(* Logix 5000 project; controller Test vendor 1 type 14 code 92 rev 33.11; software revision 33.03; part 2 of 2 *)
(* tags used below, declared in another part *)
   B25 : Banner_B25_v4;
   Port_Data : Banner_IOL_Port_v4;
   Port : DINT;
   Local_Control : DINT;
   Command_Being_Processed : BOOL;
   Index_Write_Inprocess : INT;
   Inprocess_Index : DINT;
(* Banner_B25_Param_v4, continued *)

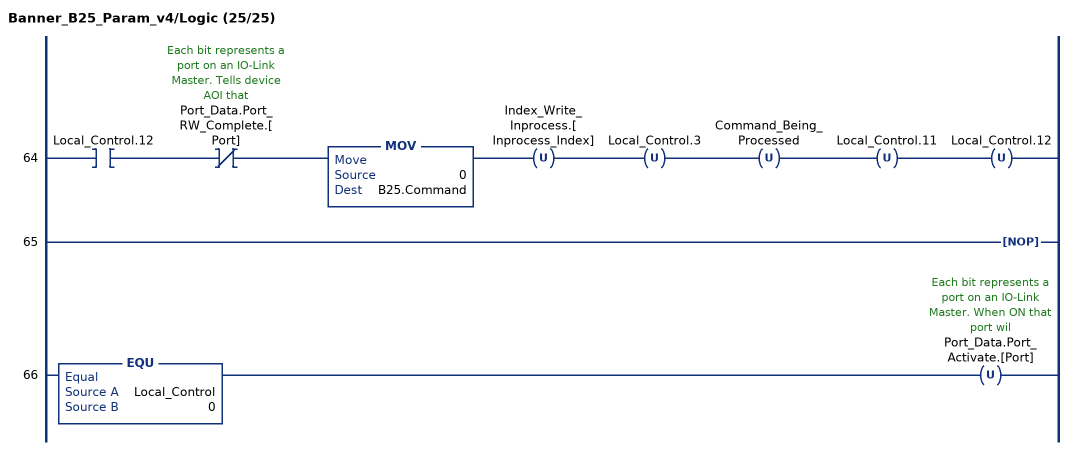
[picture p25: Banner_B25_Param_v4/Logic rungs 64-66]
   64: XIC(Local_Control.12)XIO(Port_Data.Port_RW_Complete.[Port])MOV(0,B25.Command)OTU(Index_Write_Inprocess.[Inprocess_Index])OTU(Local_Control.3)OTU(Command_Being_Processed)OTU(Local_Control.11)OTU(Local_Control.12);
   65: NOP();
   66: EQU(Local_Control,0)OTU(Port_Data.Port_Activate.[Port]);
END_ROUTINE
END_ADD_ON_INSTRUCTION

ADD_ON_INSTRUCTION Banner_B25_PD_v4   (* revision 4.0, vendor Banner Engineering *)
// Take raw process data and convert it to usable values.
VAR_INPUT
   SINT0 : SINT; {required}
END_VAR
VAR_IN_OUT
   PD : Banner_B25_PDI_v4; {required}
END_VAR

ROUTINE Logic   (* ladder *)
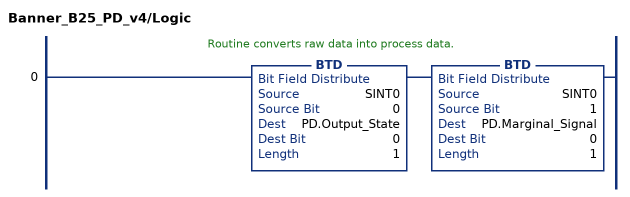
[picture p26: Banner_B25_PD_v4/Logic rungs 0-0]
   // Routine converts raw data into process data.
   0: BTD(SINT0,0,PD.Output_State,0,1)BTD(SINT0,1,PD.Marginal_Signal,0,1);
END_ROUTINE
END_ADD_ON_INSTRUCTION

ADD_ON_INSTRUCTION Banner_DXMR_IOLM_Param_v4   (* revision 4.3, vendor Banner Engineering *)
// AOI that controls a Banner IO-Link Master with Banner devices for parameter data operations.
// Revision note:
// Updated name of AOI.
VAR_IN_OUT
   IOLM : Banner_IOLM_v4; {required}
END_VAR
VAR
   Lock : DINT; {access None}
   Byte_Length : SINT; {access None}
   Current_Port : INT; {access None}   // Current port to communicate with via the IO-Link Master.
   Timer1 : TIMER := (PRE := 500); {access None}
   Error_Index : DINT; {access None}
   Timer2 : TIMER := (PRE := 5000); {access None}
   Temp_Index : INT; {access None}
   ErrCount : DINT; {access None}
   Timer4 : TIMER := (PRE := 2000); {access None}
   Timer5 : TIMER := (PRE := 2000); {access None}
   Timer3 : TIMER := (PRE := 2000); {access None}
   Timer6 : TIMER := (PRE := 3000); {access None}
   Timer7 : TIMER := (PRE := 3000); {access None}
   Timer8 : TIMER := (PRE := 3000); {access None}
END_VAR

ROUTINE Logic   (* ladder *)
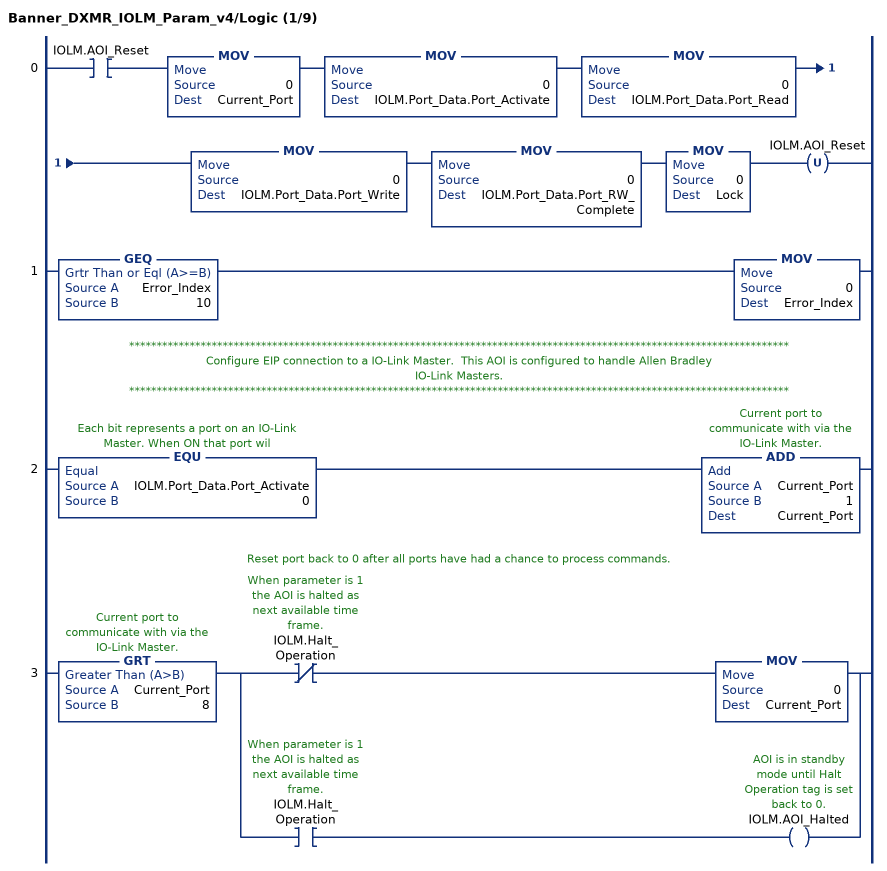
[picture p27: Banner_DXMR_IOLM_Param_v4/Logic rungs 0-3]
   0: XIC(IOLM.AOI_Reset)MOV(0,Current_Port)MOV(0,IOLM.Port_Data.Port_Activate)MOV(0,IOLM.Port_Data.Port_Read)MOV(0,IOLM.Port_Data.Port_Write)MOV(0,IOLM.Port_Data.Port_RW_Complete)MOV(0,Lock)OTU(IOLM.AOI_Reset);
   1: GEQ(Error_Index,10)MOV(0,Error_Index);
   // ************************************************************************************************************************
   // Configure EIP connection to a IO-Link Master.  This AOI is configured to handle Allen Bradley
   // IO-Link Masters.
   // ************************************************************************************************************************
   2: EQU(IOLM.Port_Data.Port_Activate,0)ADD(Current_Port,1,Current_Port);
   // Reset port back to 0 after all ports have had a chance to process commands.
   3: GRT(Current_Port,8)[XIO(IOLM.Halt_Operation) MOV(0,Current_Port) ,XIC(IOLM.Halt_Operation) OTE(IOLM.AOI_Halted) ];
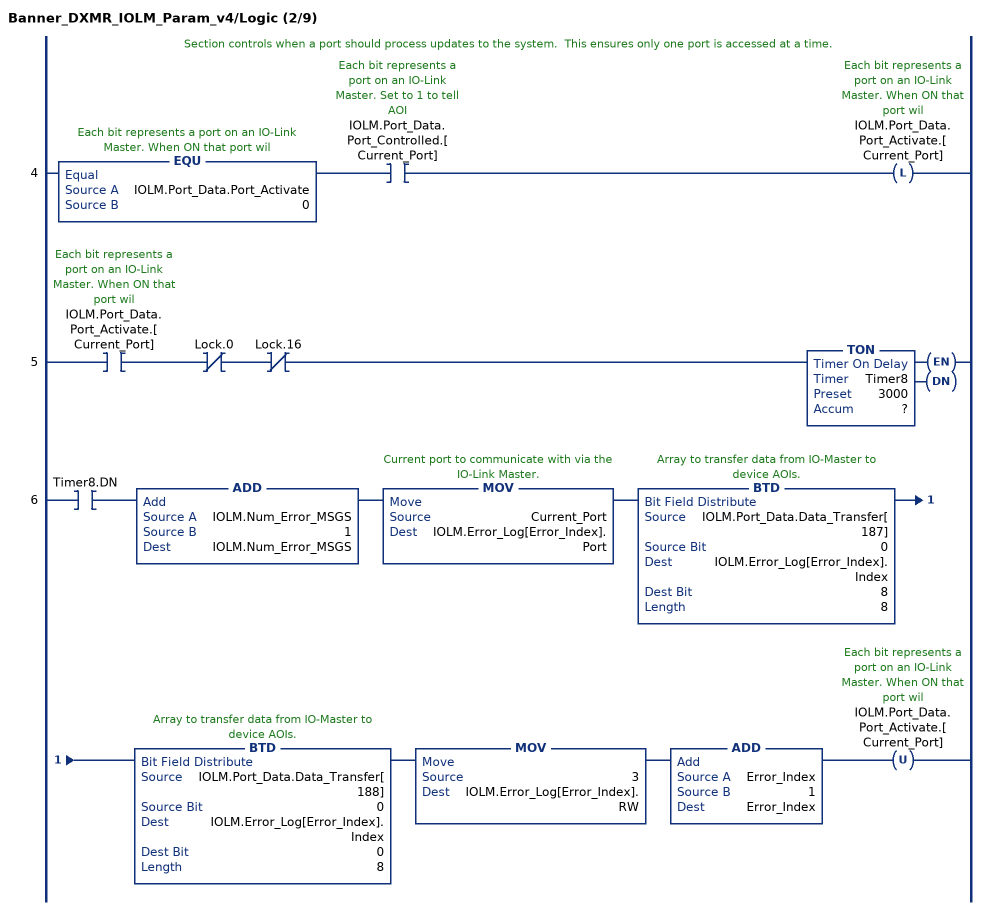
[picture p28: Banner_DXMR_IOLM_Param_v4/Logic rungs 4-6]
   // Section controls when a port should process updates to the system.  This ensures only one port is accessed at a time.
   4: EQU(IOLM.Port_Data.Port_Activate,0)XIC(IOLM.Port_Data.Port_Controlled.[Current_Port])OTL(IOLM.Port_Data.Port_Activate.[Current_Port]);
   5: XIC(IOLM.Port_Data.Port_Activate.[Current_Port])XIO(Lock.0)XIO(Lock.16)TON(Timer8,?,?);
   6: XIC(Timer8.DN)ADD(IOLM.Num_Error_MSGS,1,IOLM.Num_Error_MSGS)MOV(Current_Port,IOLM.Error_Log[Error_Index].Port)BTD(IOLM.Port_Data.Data_Transfer[187],0,IOLM.Error_Log[Error_Index].Index,8,8)BTD(IOLM.Port_Data.Data_Transfer[188],0,IOLM.Error_Log[Error_Index].Index,0,8)MOV(3,IOLM.Error_Log[Error_Index].RW)ADD(Error_Index,1,Error_Index)OTU(IOLM.Port_Data.Port_Activate.[Current_Port]);
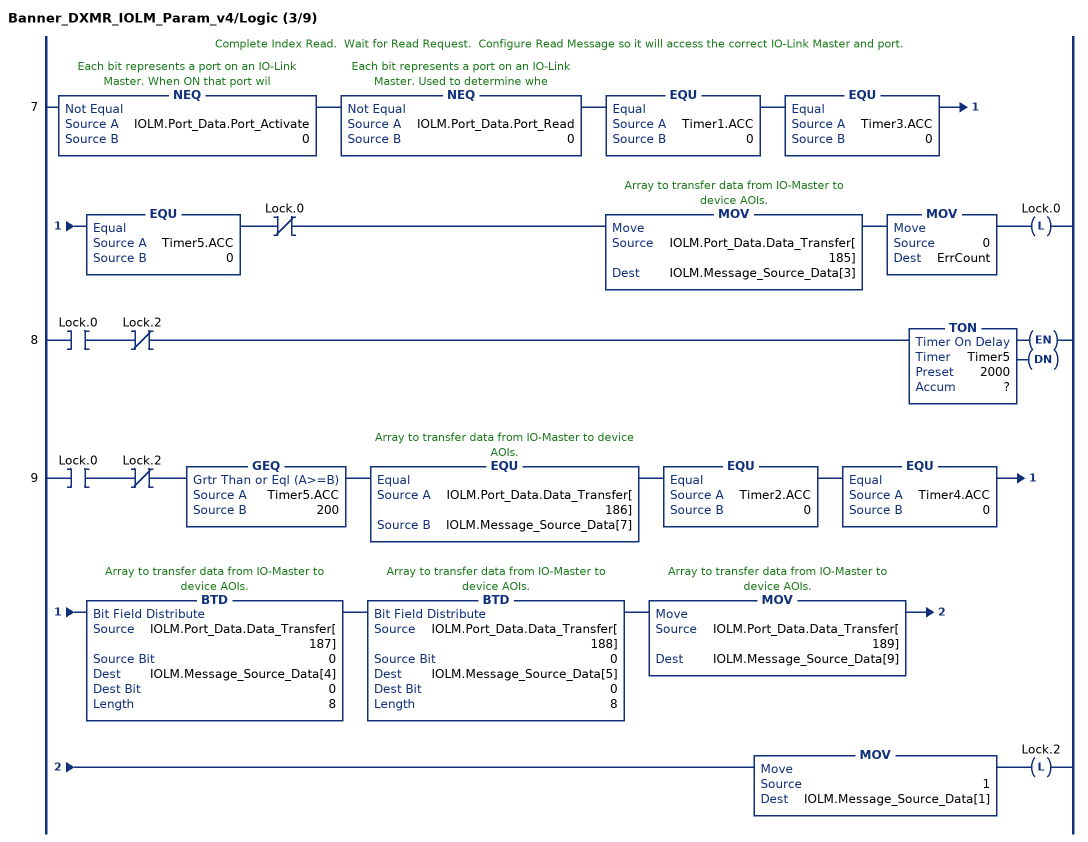
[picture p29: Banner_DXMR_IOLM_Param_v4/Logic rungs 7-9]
   // Complete Index Read.  Wait for Read Request.  Configure Read Message so it will access the correct IO-Link Master and port.
   7: NEQ(IOLM.Port_Data.Port_Activate,0)NEQ(IOLM.Port_Data.Port_Read,0)EQU(Timer1.ACC,0)EQU(Timer3.ACC,0)EQU(Timer5.ACC,0)XIO(Lock.0)MOV(IOLM.Port_Data.Data_Transfer[185],IOLM.Message_Source_Data[3])MOV(0,ErrCount)OTL(Lock.0);
   8: XIC(Lock.0)XIO(Lock.2)TON(Timer5,?,?);
   9: XIC(Lock.0)XIO(Lock.2)GEQ(Timer5.ACC,200)EQU(IOLM.Port_Data.Data_Transfer[186],IOLM.Message_Source_Data[7])EQU(Timer2.ACC,0)EQU(Timer4.ACC,0)BTD(IOLM.Port_Data.Data_Transfer[187],0,IOLM.Message_Source_Data[4],0,8)BTD(IOLM.Port_Data.Data_Transfer[188],0,IOLM.Message_Source_Data[5],0,8)MOV(IOLM.Port_Data.Data_Transfer[189],IOLM.Message_Source_Data[9])MOV(1,IOLM.Message_Source_Data[1])OTL(Lock.2);
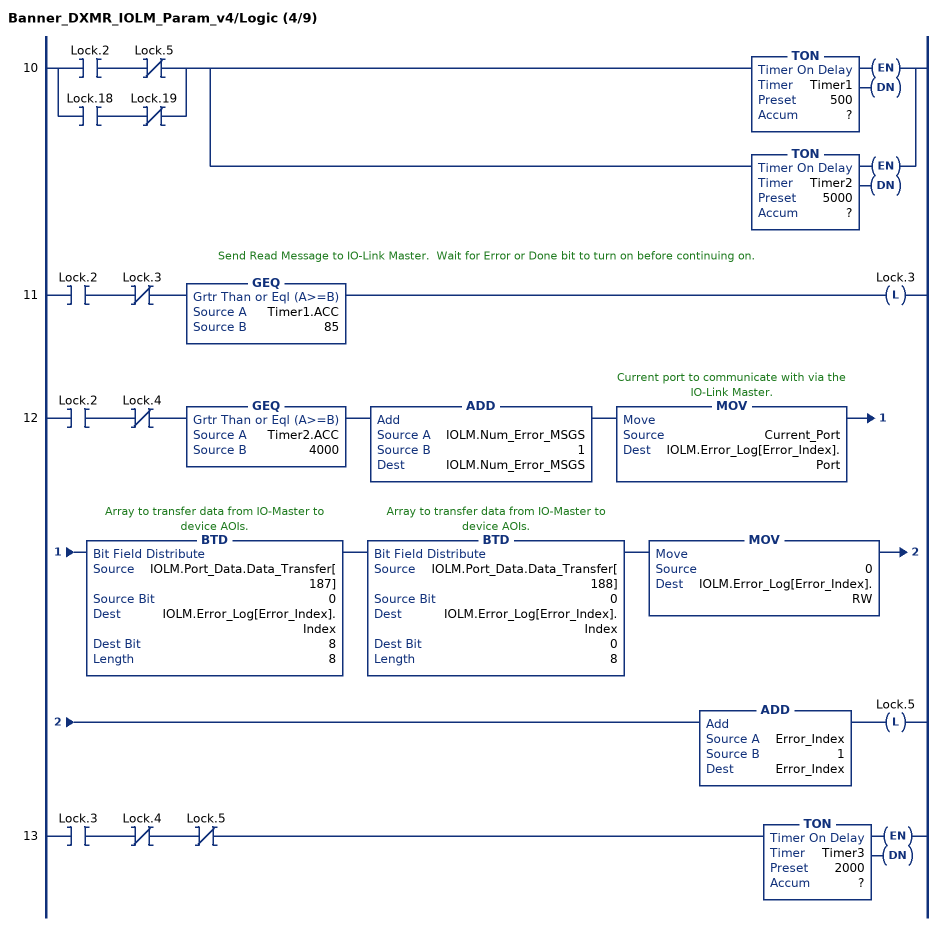
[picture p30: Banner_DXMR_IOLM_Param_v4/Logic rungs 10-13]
   10: [XIC(Lock.2) XIO(Lock.5) ,XIC(Lock.18) XIO(Lock.19) ][TON(Timer1,?,?) ,TON(Timer2,?,?) ];
   // Send Read Message to IO-Link Master.  Wait for Error or Done bit to turn on before continuing on.
   11: XIC(Lock.2)XIO(Lock.3)GEQ(Timer1.ACC,85)OTL(Lock.3);
   12: XIC(Lock.2)XIO(Lock.4)GEQ(Timer2.ACC,4000)ADD(IOLM.Num_Error_MSGS,1,IOLM.Num_Error_MSGS)MOV(Current_Port,IOLM.Error_Log[Error_Index].Port)BTD(IOLM.Port_Data.Data_Transfer[187],0,IOLM.Error_Log[Error_Index].Index,8,8)BTD(IOLM.Port_Data.Data_Transfer[188],0,IOLM.Error_Log[Error_Index].Index,0,8)MOV(0,IOLM.Error_Log[Error_Index].RW)ADD(Error_Index,1,Error_Index)OTL(Lock.5);
   13: XIC(Lock.3)XIO(Lock.4)XIO(Lock.5)TON(Timer3,?,?);
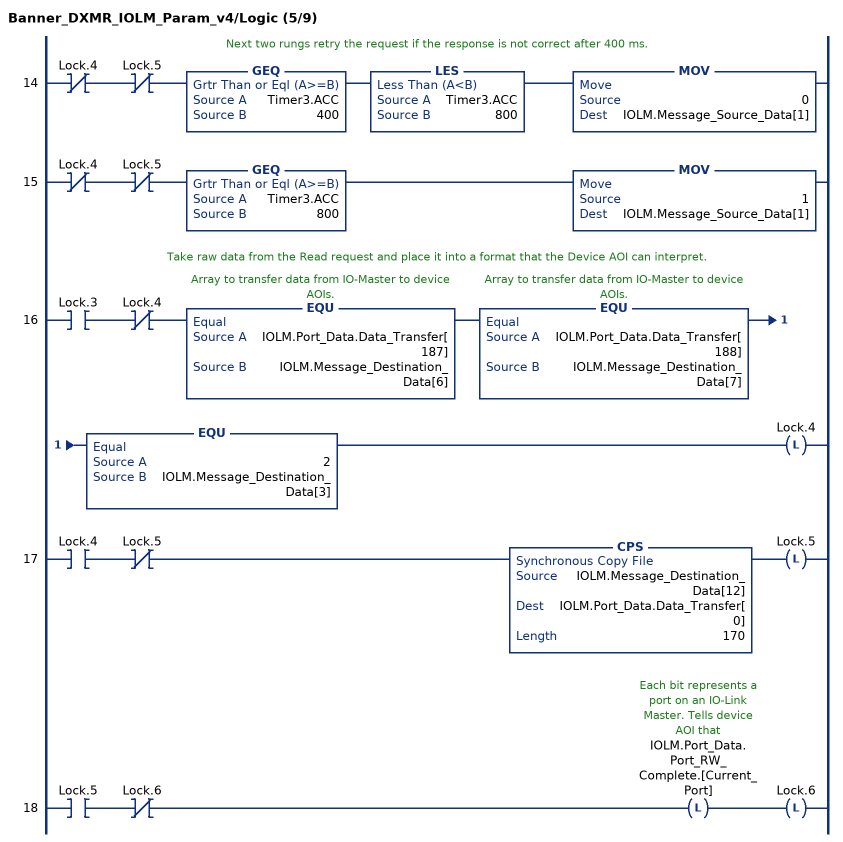
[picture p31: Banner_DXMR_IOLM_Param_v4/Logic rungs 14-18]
   // Next two rungs retry the request if the response is not correct after 400 ms.
   14: XIO(Lock.4)XIO(Lock.5)GEQ(Timer3.ACC,400)LES(Timer3.ACC,800)MOV(0,IOLM.Message_Source_Data[1]);
   15: XIO(Lock.4)XIO(Lock.5)GEQ(Timer3.ACC,800)MOV(1,IOLM.Message_Source_Data[1]);
   // Take raw data from the Read request and place it into a format that the Device AOI can interpret.
   16: XIC(Lock.3)XIO(Lock.4)EQU(IOLM.Port_Data.Data_Transfer[187],IOLM.Message_Destination_Data[6])EQU(IOLM.Port_Data.Data_Transfer[188],IOLM.Message_Destination_Data[7])EQU(2,IOLM.Message_Destination_Data[3])OTL(Lock.4);
   17: XIC(Lock.4)XIO(Lock.5)CPS(IOLM.Message_Destination_Data[12],IOLM.Port_Data.Data_Transfer[0],170)OTL(Lock.5);
   18: XIC(Lock.5)XIO(Lock.6)OTL(IOLM.Port_Data.Port_RW_Complete.[Current_Port])OTL(Lock.6);
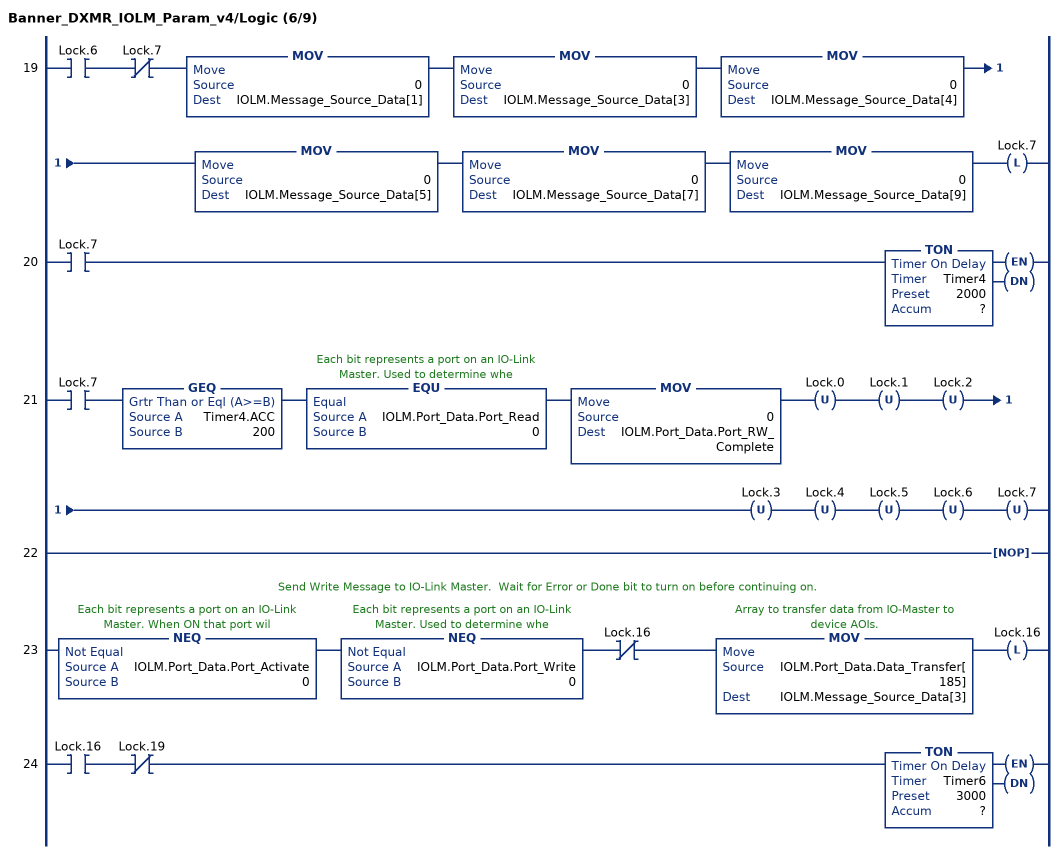
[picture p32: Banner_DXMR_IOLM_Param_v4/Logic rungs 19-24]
   19: XIC(Lock.6)XIO(Lock.7)MOV(0,IOLM.Message_Source_Data[1])MOV(0,IOLM.Message_Source_Data[3])MOV(0,IOLM.Message_Source_Data[4])MOV(0,IOLM.Message_Source_Data[5])MOV(0,IOLM.Message_Source_Data[7])MOV(0,IOLM.Message_Source_Data[9])OTL(Lock.7);
   20: XIC(Lock.7)TON(Timer4,?,?);
   21: XIC(Lock.7)GEQ(Timer4.ACC,200)EQU(IOLM.Port_Data.Port_Read,0)MOV(0,IOLM.Port_Data.Port_RW_Complete)OTU(Lock.0)OTU(Lock.1)OTU(Lock.2)OTU(Lock.3)OTU(Lock.4)OTU(Lock.5)OTU(Lock.6)OTU(Lock.7);
   22: NOP();
   // Send Write Message to IO-Link Master.  Wait for Error or Done bit to turn on before continuing on.
   23: NEQ(IOLM.Port_Data.Port_Activate,0)NEQ(IOLM.Port_Data.Port_Write,0)XIO(Lock.16)MOV(IOLM.Port_Data.Data_Transfer[185],IOLM.Message_Source_Data[3])OTL(Lock.16);
   24: XIC(Lock.16)XIO(Lock.19)TON(Timer6,?,?);
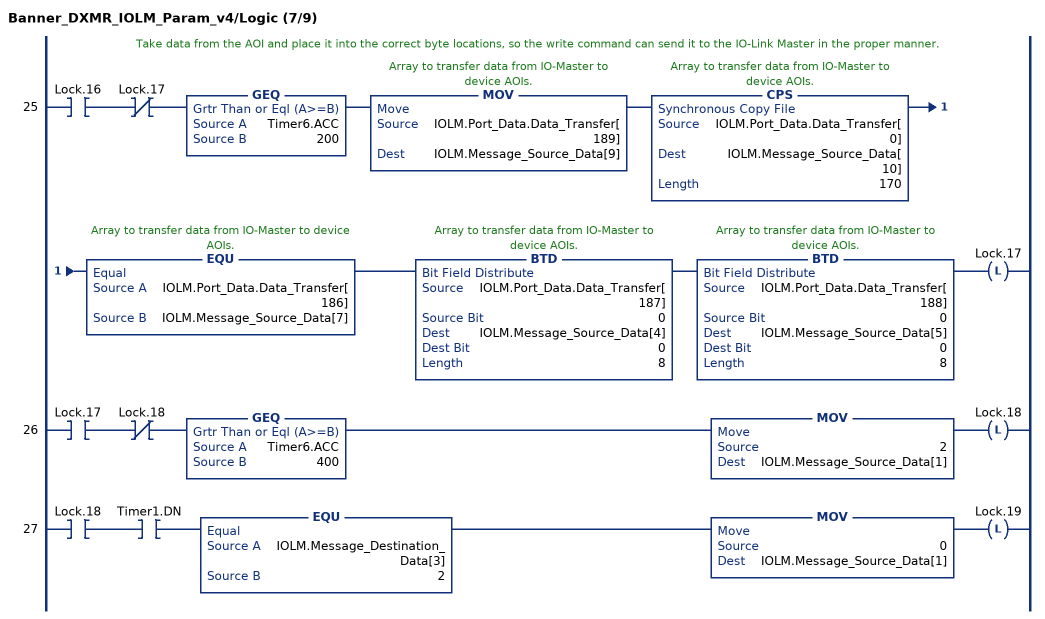
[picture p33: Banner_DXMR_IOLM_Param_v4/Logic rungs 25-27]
   // Take data from the AOI and place it into the correct byte locations, so the write command can send it to the IO-Link Master in the proper manner.
   25: XIC(Lock.16)XIO(Lock.17)GEQ(Timer6.ACC,200)MOV(IOLM.Port_Data.Data_Transfer[189],IOLM.Message_Source_Data[9])CPS(IOLM.Port_Data.Data_Transfer[0],IOLM.Message_Source_Data[10],170)EQU(IOLM.Port_Data.Data_Transfer[186],IOLM.Message_Source_Data[7])BTD(IOLM.Port_Data.Data_Transfer[187],0,IOLM.Message_Source_Data[4],0,8)BTD(IOLM.Port_Data.Data_Transfer[188],0,IOLM.Message_Source_Data[5],0,8)OTL(Lock.17);
   26: XIC(Lock.17)XIO(Lock.18)GEQ(Timer6.ACC,400)MOV(2,IOLM.Message_Source_Data[1])OTL(Lock.18);
   27: XIC(Lock.18)XIC(Timer1.DN)EQU(IOLM.Message_Destination_Data[3],2)MOV(0,IOLM.Message_Source_Data[1])OTL(Lock.19);
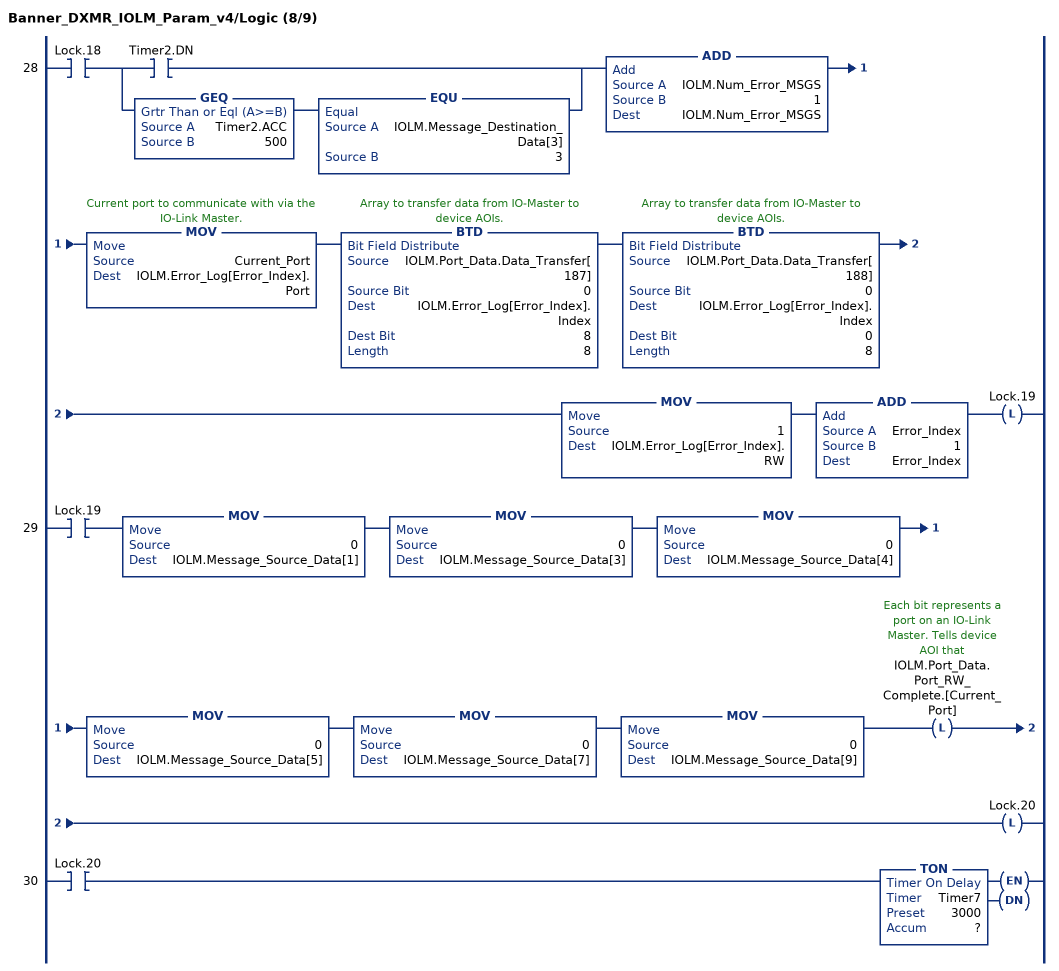
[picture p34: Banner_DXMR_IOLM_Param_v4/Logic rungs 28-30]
   28: XIC(Lock.18)[XIC(Timer2.DN) ,GEQ(Timer2.ACC,500) EQU(IOLM.Message_Destination_Data[3],3) ]ADD(IOLM.Num_Error_MSGS,1,IOLM.Num_Error_MSGS)MOV(Current_Port,IOLM.Error_Log[Error_Index].Port)BTD(IOLM.Port_Data.Data_Transfer[187],0,IOLM.Error_Log[Error_Index].Index,8,8)BTD(IOLM.Port_Data.Data_Transfer[188],0,IOLM.Error_Log[Error_Index].Index,0,8)MOV(1,IOLM.Error_Log[Error_Index].RW)ADD(Error_Index,1,Error_Index)OTL(Lock.19);
   29: XIC(Lock.19)MOV(0,IOLM.Message_Source_Data[1])MOV(0,IOLM.Message_Source_Data[3])MOV(0,IOLM.Message_Source_Data[4])MOV(0,IOLM.Message_Source_Data[5])MOV(0,IOLM.Message_Source_Data[7])MOV(0,IOLM.Message_Source_Data[9])OTL(IOLM.Port_Data.Port_RW_Complete.[Current_Port])OTL(Lock.20);
   30: XIC(Lock.20)TON(Timer7,?,?);
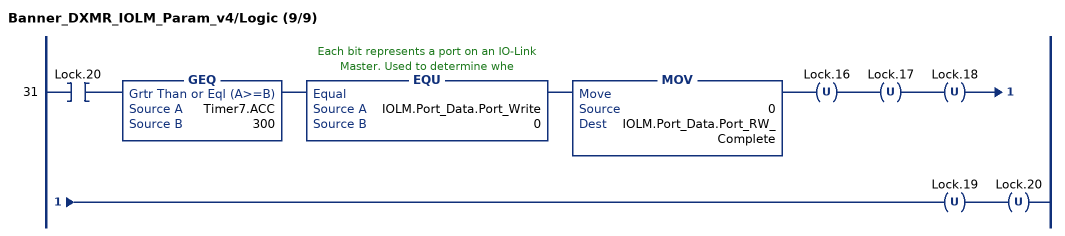
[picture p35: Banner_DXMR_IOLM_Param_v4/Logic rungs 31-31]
   31: XIC(Lock.20)GEQ(Timer7.ACC,300)EQU(IOLM.Port_Data.Port_Write,0)MOV(0,IOLM.Port_Data.Port_RW_Complete)OTU(Lock.16)OTU(Lock.17)OTU(Lock.18)OTU(Lock.19)OTU(Lock.20);
END_ROUTINE
END_ADD_ON_INSTRUCTION

VAR_GLOBAL   (* controller tags *)
   B25_IOLM1_01 : Banner_B25_v4;
   B25_IOLM1_01_PD : Banner_B25_PDI_v4;
   B25_IOLM1_01_PD_Status : Banner_B25_PD_v4;
   B25_IOLM1_01_Status : Banner_B25_Param_v4;
   IOLM1 : Banner_IOLM_v4;
   IOLM1_Status : Banner_DXMR_IOLM_Param_v4;
   Reset : BOOL;
END_VAR

PROGRAM MainProgram   (* main routine MainRoutine *)

ROUTINE MainRoutine   (* ladder *)
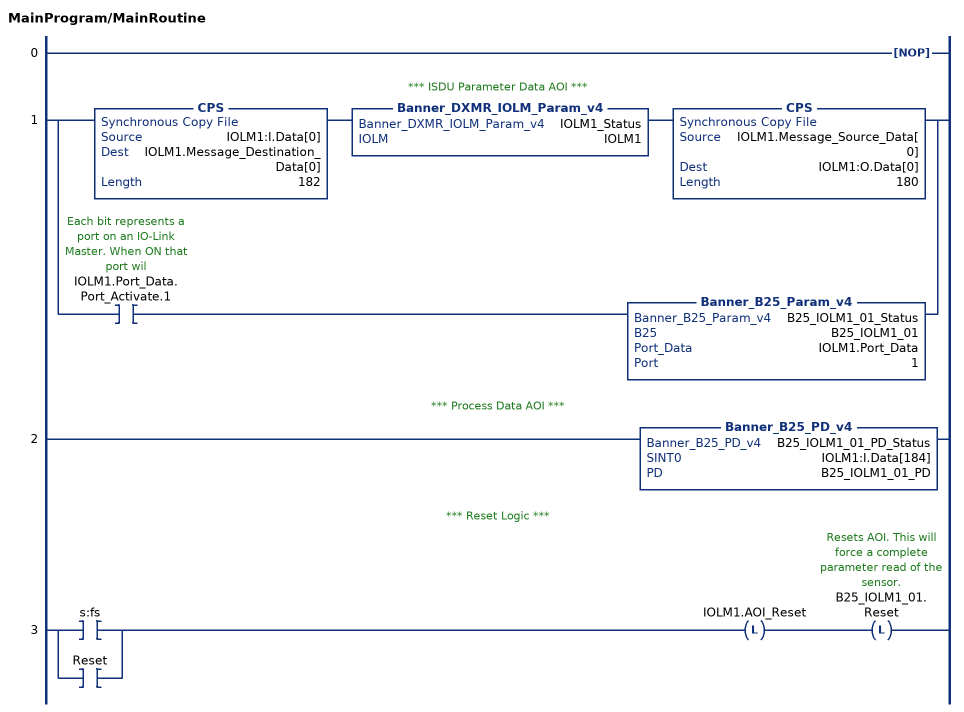
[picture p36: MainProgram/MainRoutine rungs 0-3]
   0: NOP();
   // *** ISDU Parameter Data AOI ***
   1: [CPS(IOLM1:I.Data[0],IOLM1.Message_Destination_Data[0],182) Banner_DXMR_IOLM_Param_v4(IOLM1_Status,IOLM1) CPS(IOLM1.Message_Source_Data[0],IOLM1:O.Data[0],180) ,XIC(IOLM1.Port_Data.Port_Activate.1) Banner_B25_Param_v4(B25_IOLM1_01_Status,B25_IOLM1_01,IOLM1.Port_Data,1) ];
   // *** Process Data AOI ***
   2: Banner_B25_PD_v4(B25_IOLM1_01_PD_Status,IOLM1:I.Data[184],B25_IOLM1_01_PD);
   // *** Reset Logic ***
   3: [XIC(s:fs) ,XIC(Reset) ]OTL(IOLM1.AOI_Reset)OTL(B25_IOLM1_01.Reset);
END_ROUTINE
END_PROGRAM
